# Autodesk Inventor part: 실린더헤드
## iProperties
Manager: KYOUNG IL JANG
Company: 한국ATC센터
Created: 2012-10
Part Number: 실린더헤드
Document SubType Name: Modeling
Density: 1 g/cm^3
Checked By: KYOUNG IL JANG
Vendor: CBT Solutions
Designer: KYOUNG IL JANG
Author: KYOUNG IL JANG
